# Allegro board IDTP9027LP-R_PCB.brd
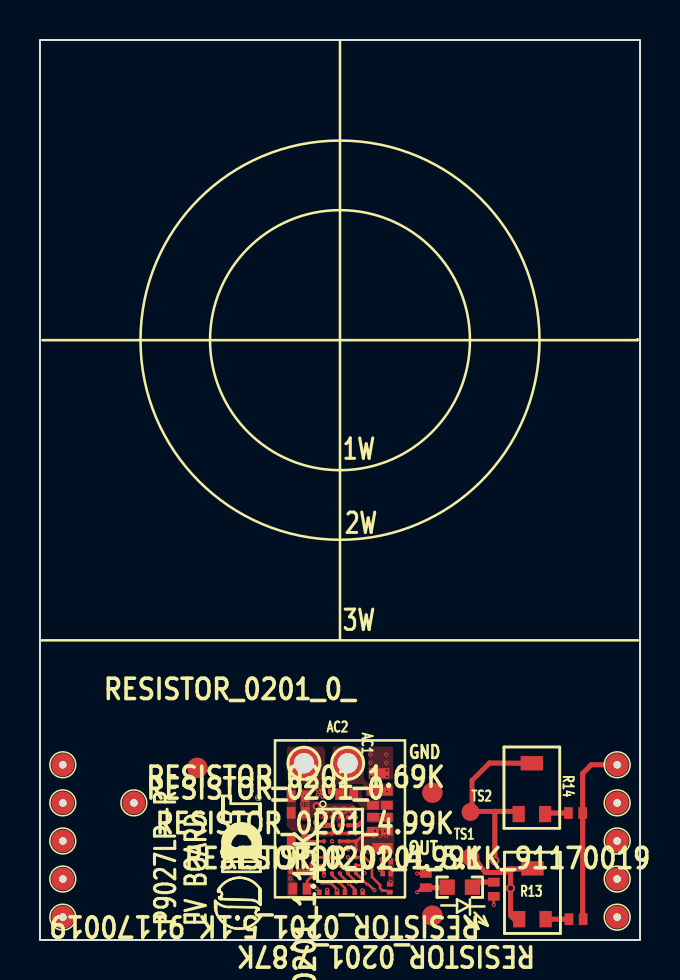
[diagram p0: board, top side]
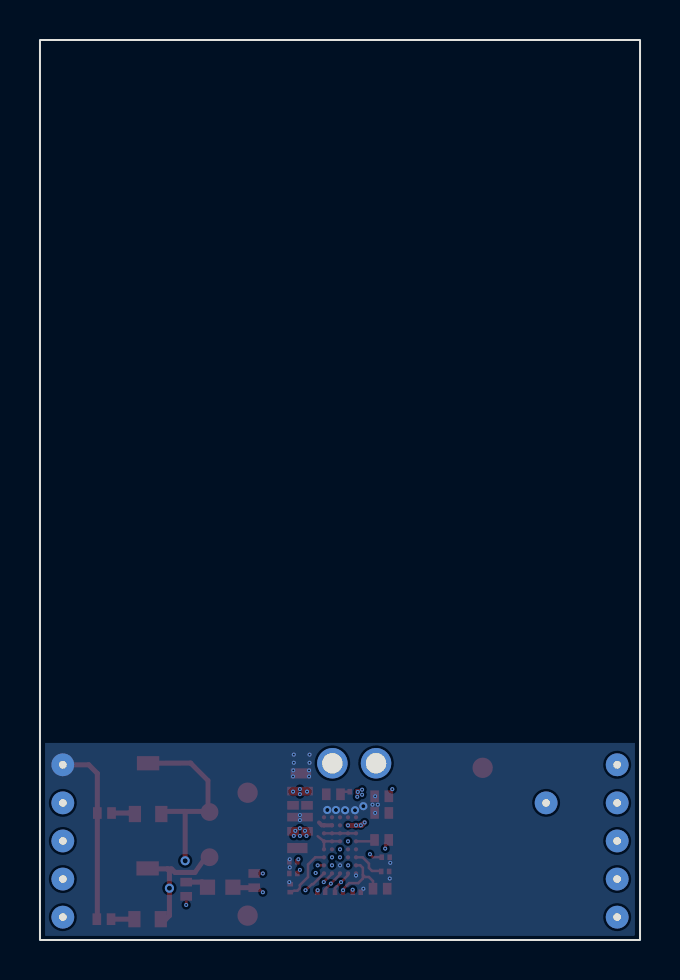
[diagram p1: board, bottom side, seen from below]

Outline 30.02 x 45.01 mm; copper layers: TOP, MID-1, MID-2, BOTTOM. Coordinates in mm from the lower left corner of the outline.
Outline path: rectangle 0,0 30.02,45.01

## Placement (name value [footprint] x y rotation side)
AC1  28AWG  [TP_40]  15.39 8.84 0 top
AC2  28AWG  [TP_40]  13.21 8.84 0 top
C1  10uF/16V  [0402]  12.92 7.19 0 top
C2  10uF/16V  [0402]  12.92 6.35 0 top
C3  0.047uF  [0402]  12.93 5 180 top
C4  1uF  [0402]  13 2.57 180 top
C5  0 ohm  [0402]  16.66 7.09 270 top
C6  10uF/16V  [0402]  16.66 5.79 90 top
C7  10uF/16V  [0402]  17.36 5.79 90 top
C8  0 ohm  [0402]  17.36 7.09 270 top
C9  1800pF  [0402]  15.34 7.29 180 top
D1  LED  [0402_LED]  21.01 2.64 0 top
EOC  28AWG  [15MIL_45PAD]  1.14 6.86 0 top
GND  1P  [15MIL_45PAD]  28.88 8.76 0 top
GNDS  SOLDER PAD  [PAD30X60]  16.97 8.33 0 top
NOREF  -  []  29.92 10.16 90 top
NOREF#2  -  []  0 0 90 top
NOREF#3  -  []  0.01 9.99 0 top
NOREF#4  -  [unnamed#2]  7.87 8.61 0 top
NOREF#5  -  []  11.76 -0.01 0 top
NOREF#6  -  []  -57.63 -84.28 0 top
NOREF#7  -  []  -89.31 -119.23 0 top
NOREF#8  -  [unnamed#2]  19.63 7.37 0 top
NOREF#9  -  [unnamed#2]  19.63 1.22 0 top
OUT  1P  [15MIL_45PAD]  28.88 6.86 0 top
OUT1  SOLDER PAD  [PAD30X60]  17.14 4.6 0 top
OUTS  1P  [15MIL_45PAD]  28.88 4.95 0 top
R1  5.1k  [0201]  15.95 2.39 0 top
R2  5.1k  [0201]  15.06 2.39 180 top
R3  680  [0402]  22.71 2.54 90 top
R4  5.1k  [0402]  19.3 2.97 270 top
R5  0  [0201]  14.33 7.42 0 top
R6  4.99K  [0201]  14.17 2.39 0 top
R7  4.99K  [0201]  12.73 4.14 0 top
R8  1.13k  [0201]  17.5 2.59 90 top
R9  0  [0201]  17.35 3.33 0 top
R10  7.87K  [0201]  12.75 3.43 180 top
R11  2.49K  [0402]  26.82 1.04 0 top
R12  1.69k  [0201]  17.35 3.91 0 top
R13  10k  [PVA2A]  24.64 2.36 0 top
R14  10k  [PVA2A]  24.61 7.62 0 top
R15  2.49K  [0402]  26.8 6.35 0 top
RECT  28AWG  [15MIL_45PAD]  1.14 8.76 0 top
SCL  28AWG  [15MIL_45PAD]  1.14 4.95 0 top
SDA  28AWG  [15MIL_45PAD]  1.14 3.05 0 top
TS1  28AWG  [35MIL_SMD]  21.54 4.14 0 top
TS2  28AWG  [35MIL_SMD]  21.54 6.4 0 top
U1  P9027LP  [IDTP9027CSP]  15.01 4.74 270 top
UNK/ACT  28AWG  [15MIL_45PAD]  28.88 3.05 0 top
UNK/EN  28AWG  [15MIL_45PAD]  1.14 1.14 0 top
UNK/INT  28AWG  [15MIL_45PAD]  4.7 6.86 0 top
VDD  28AWG  [15MIL_45PAD]  28.88 1.14 0 top

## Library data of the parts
AC1 AC2 EOC RECT SCL SDA TS1 TS2 UNK/ACT UNK/EN UNK/INT VDD = PTH
C1 C2 = CAP
C3 C4 C6 C7 C9 = CAP: tolerance: 20%
C5 C8 = CAP: tolerance: 10%
D1 = Green_LED
GND OUT OUTS = TP_TH_1P
GNDS OUT1 = TEST POINT
R1-R12 R15 = RESISTOR
R13 R14 = RESISTOR VAR
U1 = idt9027_WCSP40P_8

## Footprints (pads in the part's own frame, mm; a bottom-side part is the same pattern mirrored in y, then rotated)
15MIL_45PAD
  round 1.143 hole 0.381: 1(0,0)
35MIL_SMD
  round 0.889 smd: 1(0,0)
0201
  rect 0.229x0.279 smd: 1(-0.198,0) 2(0.198,0)
0402
  rect 0.432x0.584 smd: 1(-0.356,0) 2(0.356,0)
0402_LED
  rect 0.762x0.762 smd: 1(-0.635,0) 2(0.635,0)
IDTP9027CSP
  round 0.215 smd: A1(-1.4,-0.8) A2(-1.4,-0.4) A3(-1.4,0) A4(-1.4,0.4) A5(-1.4,0.8) B1(-1,-0.8) B2(-1,-0.4) B3(-1,0) B4(-1,0.4) B5(-1,0.8) C1(-0.6,-0.8) C2(-0.6,-0.4) C3(-0.6,0) C4(-0.6,0.4) C5(-0.6,0.8) D1(-0.2,-0.8) D2(-0.2,-0.4) D3(-0.2,0) D4(-0.2,0.4) D5(-0.2,0.8) E1(0.2,-0.8) E2(0.2,-0.4) E3(0.2,0) E4(0.2,0.4) E5(0.2,0.8) F1(0.6,-0.8) F2(0.6,-0.4) F3(0.6,0) F4(0.6,0.4) F5(0.6,0.8) G1(1,-0.8) G2(1,-0.4) G3(1,0) G4(1,0.4) G5(1,0.8) H1(1.4,-0.8) H2(1.4,-0.4) H3(1.4,0) H4(1.4,0.4) H5(1.4,0.8)
PAD30X60
  rect 1.016x0.508 smd: 1(0,0)
PVA2A
  rect 0.61x0.813 smd: 1(-0.66,-1.321) 3(0.66,-1.321)
  rect 1.118x0.711 smd: 2(0,1.219)
TP_40
  round 1.524 hole 1.016: 1(0,0)
unnamed#2
  round 1.016 smd: (0,0)

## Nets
GND: C1.2 C2.2 C4.2 C6.2 C7.2 GND.1 GNDS.1 R6.1 R7.1 R8.2 R9.2 R10.2 R11.2 R12.2 R15.2 U1.A1(PGND) U1.A2(PGND_1) U1.A3(PGND_2) U1.A4(PGND_3) U1.A5(PGND_4) U1.B3(PGND_5) U1.G3(AGND1) U1.H1(AGND)
AC1: C5.2 C8.2 C9.1 U1.B4(LX1) U1.B5(LX1_1)
AC2: AC2.1 R5.1 U1.B1(LX2) U1.B2(LX2_1)
N8022721: C6.1 C7.1 OUT.1 OUT1.1 OUTS.1 U1.D3(OUT) U1.D4(OUT_1) U1.D5(OUT_2) U1.E5(OUTSNS)
N8024318: C1.1 C2.1 RECT.1 U1.C1(VRECT) U1.C2(VRECT_1) U1.C3(VRECT_2) U1.C4(VRECT_3) U1.C5(VRECT_4)
N8024357: R13.1(A) R13.2(WIPER) TS1.1 U1.G5(TS1)
N8074748: C4.1 D1.1(ANODE) R1.2 R2.2 R4.2 U1.G1(VDD) VDD.1
N8274034: C3.1 U1.D1(CFLY2)
N8274039: C3.2 U1.D2(CFLY1)
N8286100: R10.1 U1.F1(IOC)
N8286112: R9.1 U1.F4(VSET)
N8286122: R8.1 U1.F5(VHDR)
N8290798: R4.1 U1.H4(INT_B) UNK/INT.1
N8292776: EOC.1 R7.2 U1.F3(EOC)
N8387544: R6.2 U1.G2(/EN) UNK/EN.1
N8395614: R14.1(A) R14.2(WIPER) TS2.1 U1.G4(TS2)
N8404186: R1.1 SCL.1 U1.H3(SCL)
N8404206: R2.1 SDA.1 U1.H2(SDA)
N8406126: R12.1 U1.E3(RSVD)
N8415857: R3.1 U1.H5(ACT_B) UNK/ACT.1
N8419351: AC1.1 C5.1 C8.1
N8435328: C9.2 R5.2
N80671141: D1.2(CATHODE) R3.2
N84247281: R14.3(B) R15.1
N84250351: R11.1 R13.3(B)

Pads without a net: U1 E1 E2 E4 F2

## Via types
v1: diameter 0.203, hole 0.102, TOP to BOTTOM, 63 vias
v2: diameter 0.457, hole 0.254, TOP to BOTTOM, 2 vias
v3: diameter 0.406, hole 0.203, TOP to BOTTOM, 5 vias

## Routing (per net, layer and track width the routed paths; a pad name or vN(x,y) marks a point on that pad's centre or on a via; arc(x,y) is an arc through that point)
GND: length 9.6
  TOP w0.127: U1.H1 v1(14.21,3.23) ; R6.1 13.82,2.54 v1(13.84,2.57)
  TOP w0.254: GND.1 27.58,8.76 27.15,8.33 R15.2 27.15,1.07 R11.2
  vias: v1(12.5,3.86) v1(12.52,3.07) v1(13.12,6.77) v1(13.25,7.19) v1(13.25,6.35) v1(13.39,6.77) v1(15.01,3.74) v1(16.54,9.27) v1(16.54,8.86) v1(16.56,8.48) v1(16.56,8.18) v1(17.02,6.25) v1(17.02,5.99) v1(17.32,9.27) v1(17.32,8.86) v1(17.35,8.48) v1(17.36,8.18) v1(17.53,4.04) v1(17.53,3.63) v1(17.55,2.9) v3(13.84,6.69) v3(14.26,6.49) v3(14.76,6.49) v3(15.21,6.5) v3(15.65,6.5)
AC1: length 0.7
  TOP w0.203: 16.06,5.88 15.92,5.74 U1.B5 U1.B4
AC2: length 0.9
  TOP w0.254: v1(14.61,5.74) v1(14.21,5.74) v1(13.97,5.74) 13.92,5.74 v1(13.78,5.88)
  vias: v1(13.91,7.52) v1(13.91,7.26) v1(14.12,7.4) v1(14.15,7.16)
N8022721: length 13.8
  TOP w0.127: U1.D5 U1.D4 U1.D3 ; U1.D5 U1.E5 ; U1.D5 16.13,5.19
  MID-2 w0.254: v1(17.02,5.21) 17.02,5 17.27,4.75 28.51,4.75 OUTS.1
  vias: v1(16.69,5.21) v1(16.76,5.46) v1(17.02,5.59) v1(17.25,5.46) v1(17.32,5.21)
N8024318: length 13.6
  TOP w0.127: U1.C5 U1.C4 U1.C3 U1.C2 U1.C1
  MID-2 w0.24: RECT.1 1.24,8.86 5.46,8.86 7,7.32 12.07,7.32 v1(12.4,7.54)
N8024357: length 16.8
  TOP w0.127: U1.G5 v1(16.13,3.73)
  TOP w0.24: 22.27,3.38 21.76,4.1 TS1.1
  TOP w0.254: R13.1 23.74,1.03 23.55,1.22 v2(23.55,2.59) 23.55,3.45 23.65,3.56 ; 23.65,3.56 24.85,3.56 R13.2 ; 23.65,3.56 23.44,3.56 23.26,3.38 22.27,3.38
  MID-2 w0.127: v2(23.55,2.59) 23.55,3.77 22.93,4.38 18.52,4.38 17.91,3.77 17.91,3.6 17.52,3.21 16.81,3.21 16.26,3.73 v1(16.13,3.73)
N8074748: length 24.4
  TOP w0.127: 13.87,3.26 13.87,3.61 14,3.74 U1.G1 ; 13.87,3.26 13.76,3.15 13.56,3.15 13.36,2.95 C4.1 ; 13.87,3.26 13.87,3.07 14.1,2.84 14.55,2.84 14.86,2.54 R2.2 ; R1.2 v1(16.13,2.49) ; v1(18.87,2.39) 19.1,2.62 R4.2
  TOP w0.254: D1.1 20.29,2.62 R4.2
  MID-1 w0.127: v1(16.13,2.49) v1(14.86,2.49)
  MID-2 w0.127: v1(16.13,2.49) 16.13,2.24 16.69,1.68 18.16,1.68 v1(18.87,2.39)
  MID-2 w0.24: VDD.1 28.63,1.37
  MID-2 w0.254: v1(14.86,2.49) 14.91,2.44 15.47,2.44 16.56,1.34 28.63,1.37
N8274034: length 1
  TOP w0.127: U1.D1 13.35,4.94 C3.1
N8274039: length 2.6
  TOP w0.127: C3.2 12.75,4.83 v1(12.75,4.57)
  MID-1 w0.127: v1(12.75,4.57) 12.95,4.94 v1(14.61,4.94)
N8286100: length 1.7
  TOP w0.127: R10.1 12.97,3.45 13.41,3.45 13.56,3.61 13.56,3.82 13.88,4.14 U1.F1
N8286112: length 2.3
  TOP w0.127: v1(17.02,3.51) 17.07,3.45 R9.1
  MID-1 w0.127: v1(15.41,4.14) 15.54,4.27 16.45,4.27 17.03,3.61 v1(17.02,3.51)
N8286122: length 2.8
  TOP w0.127: R8.1 17.3,2.46 17.14,2.46 17.02,2.59 17.02,2.74 16.61,3.15 16.61,3.77 16.25,4.14 U1.F5
N8290798: length 19.1
  TOP w0.127: U1.H4 15.41,3.31 v1(15.82,2.9) ; R4.1 v1(18.87,3.33)
  MID-2 w0.127: v1(18.87,3.33) 18.75,3.2 18.75,2.79 17.88,1.93 16.84,1.93 16.43,2.34 16.43,2.67 16.23,2.87 15.85,2.87 v1(15.82,2.9)
  MID-2 w0.254: v1(15.82,2.9) 15.82,2.97 15.77,3.02 15.77,4.48 14.92,5.33 13.58,5.33 12.74,6.17 5.49,6.17 UNK/INT.1
N8292776: length 15.7
  TOP w0.127: v1(13.51,4.29) 13.36,4.14 R7.2
  MID-1 w0.127: v1(15.01,4.14) 14.88,4.27 13.54,4.27 v1(13.51,4.29)
  MID-2 w0.254: v1(13.51,4.29) 13.51,4.42 12.8,5.13 3.1,5.13 EOC.1
N8387544: length 16.3
  TOP w0.127: U1.G2 v1(14.61,3.73)
  MID-1 w0.127: v1(14.38,2.51) 14.35,2.51 14.35,2.82 14.27,2.9 13.92,2.9 13.79,3.02 13.79,3.34 14.19,3.74 14.6,3.74 v1(14.61,3.73)
  MID-2 w0.254: UNK/EN.1 1.89,1.91 14.15,1.91 14.38,2.13 v1(14.38,2.51)
N8395614: length 18.9
  TOP w0.24: 21.57,6.43 21.62,6.48 21.62,7.98 22.47,8.83
  TOP w0.25: TS2.1 21.57,6.43 22.77,6.43
  TOP w0.254: R14.2 22.49,8.85 22.47,8.83 ; R14.1 24.08,6.43 22.77,6.43 22.76,6.42 v2(22.76,3.96)
  MID-1 w0.127: v1(16.23,3.35) 16.15,3.43 15.95,3.43 15.64,3.74 v1(15.41,3.74)
  MID-2 w0.127: v2(22.76,3.96) 22.73,3.99 18.49,3.99 18.21,3.71 18.21,3.14 17.67,2.6 17.05,2.6 v1(16.23,3.35)
N8404186: length 16.6
  TOP w0.127: R1.1 15.75,2.54 v1(15.47,2.82) 15.44,2.85 15.01,3.28 U1.H3
  MID-2 w0.127: v1(15.47,2.82) 15.47,2.86 14.94,3.39 14.49,3.39 14.19,3.69
  MID-2 w0.254: SCL.1 2.84,3.49 13.21,3.49 13.42,3.69 14.19,3.69
N8404206: length 15.2
  TOP w0.127: R2.1 15.27,2.39 15.27,2.59 v1(14.96,2.9) 14.61,3.24 U1.H2
  MID-2 w0.127: v1(14.96,2.9) 14.94,2.87 13.59,2.87
  MID-2 w0.254: SDA.1 1.73,2.69 13.41,2.69 13.59,2.87
N8406126: length 2.5
  TOP w0.127: R12.1 17.07,3.99 v1(17.09,4.04)
  MID-1 w0.127: v1(17.09,4.04) 16.67,4.54 v1(15.01,4.54)
N8415857: length 17.1
  TOP w0.127: v1(22.71,1.75) R3.1 ; U1.H5 16.35,2.79 16.41,2.79 v1(16.74,2.49)
  MID-2 w0.127: v1(16.74,2.49) 17.02,2.18 17.68,2.18 18.47,2.97 18.47,3.61 18.59,3.73 20.68,3.73 21.06,3.35
  MID-2 w0.254: UNK/ACT.1 28.47,3.15 27.33,2.01 23.88,2.01 23.62,1.75 v1(22.71,1.75) 21.41,1.75 21.06,2.11 21.06,3.35
N8419351:
  vias: v1(16.66,7.42) v1(17.02,7.55) v1(17.02,7.29) v1(17.36,7.42)
N8435328: length 0.5
  TOP w0.127: R5.2 14.86,7.42 C9.2
N80671141: length 1.2
  TOP w0.254: R3.2 21.89,2.9 D1.2
N84247281: length 1.2
  TOP w0.254: R14.3 25.57,6.35 R15.1
N84250351: length 1.2
  TOP w0.254: R11.1 R13.3

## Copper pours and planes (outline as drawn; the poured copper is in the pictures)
GND on TOP: 16.43,8.08 16.43,9.58 16.54,9.68 17.63,9.68 17.68,9.63 17.68,8.08 17.63,8.03 16.48,8.03
GND on TOP: 13.77,6.93 13.93,6.93 14.03,6.83 15.63,6.83 15.86,6.6 15.86,6.05 15.8,5.98 15.21,5.98 15.15,5.92 15.15,5.68 15.1,5.63 14.94,5.63 14.87,5.69 14.87,5.89 14.74,6.02 14.03,6.02 13.91,6.15 13.64,6.15 13.45,5.95 13.09,5.95 13,6.04 13,7.56 13.03,7.58 13.55,7.58 13.6,7.53 13.6,7.1
GND on TOP: 12.37,4.37 12.6,4.37 12.65,4.32 12.65,3.07 12.88,2.84 12.88,2.13 12.37,2.13
GND on BOTTOM: 0.3,0.2 0.25,0.25 0.25,9.86 29.77,9.86 29.77,0.23 29.74,0.2
GND on MID-1: 12.37,2.13 12.37,7.65 17.68,7.65 17.68,2.13 ; 1 cut-out
AC1 on TOP: 15.98,6.67 15.68,6.96 15.39,6.96 15.38,6.97 15.38,7.61 15.39,7.62 16.03,7.62 16.1,7.54 16.1,7.16 16.26,7.01 17.69,7.01 17.69,6.5 16.32,6.5 16.28,6.46 16.28,5.82 16.09,5.64 15.82,5.64 15.76,5.7 15.76,5.82 15.98,6.03
AC2 on TOP: 14.08,7.04 14.01,7.11 13.84,7.11 13.79,7.16 13.79,7.59 13.59,7.8 12.9,7.8 12.34,8.36 12.34,9.58 12.45,9.68 14.12,9.68 14.27,9.53 14.27,7.09 14.22,7.04
AC2 on MID-1: 12.98,5.49 12.97,5.5 12.37,5.5 12.37,7.65 14.3,7.65 14.3,7.18 14.21,7.09 12.98,7.09 12.84,6.95 12.84,6.26 13.06,6.05 14.81,6.05 14.88,5.97 14.88,5.54 14.83,5.49
AC2 on MID-2: 14.08,7.04 14,7.12 13.68,7.12 12.34,8.46 12.34,9.6 12.42,9.68 14.1,9.68 14.25,9.53 14.25,8.71 14.26,8.7 14.26,7.07 14.22,7.04
N8022721 on TOP: 16.05,4.29 15.93,4.42 15.7,4.42 15.67,4.45 15.67,4.71 15.01,4.71 14.9,4.83 14.9,5.05 15.87,5.05 16.54,5.71 17.69,5.71 17.69,5.69 17.73,5.69 17.73,4.29
N8022721 on MID-2: 16.41,5.03 16.33,5.11 16.33,5.49 16.61,5.77 17.14,5.77 19.13,7.75 29.39,7.75 29.57,7.57 29.57,6.3 29.41,6.15 28.52,6.15 27.41,5.03
N8024318 on TOP: 13.64,5.17 13.45,5.36 12.69,5.36 12.34,5.7 12.34,7.57 12.36,7.58 12.81,7.58 12.85,7.55 12.85,5.95 13.02,5.78 13.56,5.78 13.88,5.46 14.8,5.46 14.8,5.45 14.87,5.45 14.87,5.46 15.88,5.46 15.94,5.4 15.94,5.27 15.89,5.23 14.72,5.23 14.66,5.17
N8419351 on TOP: 16.31,7.14 16.28,7.16 16.28,7.62 16.13,7.77 14.71,7.77 14.63,7.85 14.63,9.63 14.68,9.68 16.08,9.68 16.21,9.55 16.21,8.08 16.45,7.84 17.69,7.84 17.69,7.14
N8419351 on MID-2: 15.78,7.14 15.13,7.79 14.85,7.79 14.72,7.91 14.72,8.65 14.73,8.66 14.73,9.6 14.81,9.68 16.05,9.68 16.18,9.55 16.18,8.59 16.19,8.57 16.19,8.09 16.45,7.84 17.53,7.84 17.53,7.14

Small or netless copper shapes (teardrops, artwork), in the pictures only: 2 on TOP

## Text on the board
BOTTOM: 04_BOTTOM
Ref Des/Assembly Bottom: ASSY_BOTTOM
Board Geometry/Soldermask Bottom: 08_SMASK_BOT
Ref Des/Silkscreen Bottom: 06_SILK_BOT | 4 | GPIO | 3
TOP: 01_TOP
Ref Des/Assembly Top: ASSY_TOP
Board Geometry/Soldermask Top: 07_SMASK_TOP
Package Geometry/Pastemask Top: 09_PASTE_TOP
Ref Des/Silkscreen Top: OUT | GND | 1W | 3W | 2W | P9027LP-R | EV BOARD | 05_SILK_TOP | 6 | 5
MID-1: 02_MID1
MID-2: 03_MID2
DIMENSION: SCORE LINE | V SCORE FROM TOP AND BOTTOM | NOTE: DO NOT BREAK BOARD AFTER ASSEMBLY. | CUSTOMER WILL, DO IT LATTER. | 7. SOLDER MASK BOTH SIDES GREEN USING LIQUID PHOTO IMAGEABLE METHOD. | 8. ALL ATWORK MEDIA SHALL BE SUPPLIED BY PACTRON. NO CHANGES WILL BE | 6. ETCH VENDOR ID, UL DESIGNATION AND DATECODE ON THE BACKSIDE. | 10. BOARD TO BE SCORED AT THE LOCATIONS INDICATED | 11. ALL 4MIL VIAS TO BE NON CONDUCTIVE FILLED AND PLATED OVER. | 9. BOARD DIMENSIONS ARE IN INCHES [MM]. | SILKSCREEN BOTH SIDES USING EPOXY BASED, WHITE NON-CONDUCTIVE SILKSCREEN. | UNLESS OTHERWISE SPECIFIED. | HOLE DIAMETERS ARE AFTER PLATING, 001 MINIMUM. | NOTE: LEGEND SHOULD BE REMOVED FROM ANY CONDUCTIVE SURFACE | TYPE FR4 PER STACKUP DETAIL, OR EQUIVALENT. | FINISH: LEAD FREE HASL OR EQUIVELENT. | ALLOWED WITHOUT SPECIFIC APPROVAL FROM IDT ENGINEERING. | BUILD IN ACCORDANCE WITH IPC 6011 & IPC 6012. CLASS 2. | LAMINATE MATERIAL SHALL MEET THE REQUIREMENTS OF IPC 4101. | V1.0 | 5. | 3. | 1. | 2. | 4. | NOTES:
DEVICE_TYPE_TOP: TITLE | DATE | LAYOUT | DESIGN | IDTP9027LP-R EV BOARD | 02/20/16 | PACTRON
User.6: R | 10mil Approx | MAKE SURE IT DOES NOT DISCONNECT TRACE ON TRACE 3. | V SCORE FROM TOP ONLY. | LAYER #1 TOP SIDE (1 OZ) | LAYER #2 MID1(0.5 OZ) | LAYER #3 MID2 (0.5 OZ) | LAYER #4 BOTTOM SIDE (1 OZ) | BOTTOM SIDE SOLDERMASK | BOTTOM SIDE SILKSCREEN | TOP SIDE SILKSCREEN | TOP SIDE SOLDERMASK | +/-3 | 31.5 MILS | SCALE = NONE | VIEW A-A
User.7: V3.3 | ECO # 64426 | 09/19/13 | NS
User.10: FIGURE | SIZE | 4.0 | 8.0 | 10.0 | 15.0 | 40.0 | DRILL CHART: TOP to BOTTOM | ALL UNITS ARE IN MILS | +3.0/-3.0 | TOLERANCE | +0.0/-4.0 | PLATED | QTY | 63 | 5 | 2 | 11
